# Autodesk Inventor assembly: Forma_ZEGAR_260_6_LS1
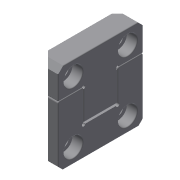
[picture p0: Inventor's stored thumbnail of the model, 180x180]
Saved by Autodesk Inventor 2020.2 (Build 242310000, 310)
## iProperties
Created: 2015-01
Part Number: Forma_ZEGAR_260_6_LS1
Document SubType Name: Assembly
Designer: F.Stasiak
Catalog Web Link: www.expertbooks.pl
Manager: www.cadconsulting.pl
Company: Fabian Stasiak CAD Consulting
Author: F.Stasiak
Subject: Zbiór ćwiczeń. Autodesk Inventor 2020. Kurs Professional
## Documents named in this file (3)
- C:\2020_Kurs_Professional\R6 Formy\Komponenty\LS\DME_FW45 1\Forma_ZEGAR_260_6_LS1.iam
- C:\2020_Kurs_Professional\R6 Formy\Komponenty\LS\DME_FW45 1\Forma_ZEGAR_260_6_LS1_FW45_F.ipt
- C:\2020_Kurs_Professional\R6 Formy\Komponenty\LS\DME_FW45 1\Forma_ZEGAR_260_6_LS1_FW45_M.ipt
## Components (2 placed, 2 different names)
1. Forma_ZEGAR_260_4_LS1_FW45_F:1 — Równoległy:1, Równoległy:2, Równoległy:3
2. Forma_ZEGAR_260_4_LS1_FW45_M:1 — Równoległy:1, Równoległy:2, Równoległy:3, Równoległy:4, Równoległy:5, Równoległy:6
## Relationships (6: Flush 6)
- Równoległy:1 [Flush]: Forma_ZEGAR_260_4_LS1_FW45_F:1 ↔ Forma_ZEGAR_260_4_LS1_FW45_M:1
- Równoległy:2 [Flush]: Forma_ZEGAR_260_4_LS1_FW45_F:1 ↔ Forma_ZEGAR_260_4_LS1_FW45_M:1
- Równoległy:3 [Flush]: Forma_ZEGAR_260_4_LS1_FW45_F:1 ↔ Forma_ZEGAR_260_4_LS1_FW45_M:1
- Równoległy:4 [Flush]: Forma_ZEGAR_260_4_LS1_FW45_M:1
- Równoległy:5 [Flush]: Forma_ZEGAR_260_4_LS1_FW45_M:1
- Równoległy:6 [Flush]: Forma_ZEGAR_260_4_LS1_FW45_M:1
